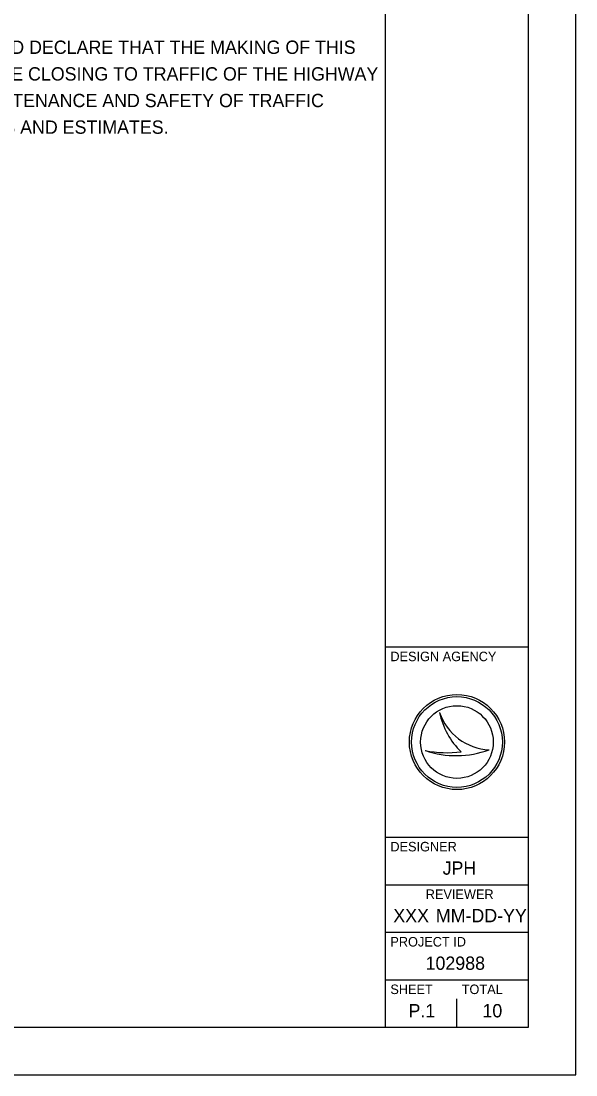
# Model space of a CAD drawing. Extents: x -2.1 to 31.9, y 6.3 to 28.3.
# Drawn here: x 26.1 to 31.93, y 6.34 to 17.42 of the extents above; entities that cross this region are included whole.
import ezdxf

# ---------------------------------------------------------------- set-up
doc = ezdxf.new("R2010")
doc.units = 0
for name, color, linetype in [('SH_Border', 7, 'Continuous'), ('SH_Cut_Line', 7, 'Continuous'), ('SH_Data', 7, 'Continuous')]:
    doc.layers.add(name, color=color, linetype=linetype)

msp = doc.modelspace()

# ---------------------------------------------------------------- linework, layer by layer
at = {"layer": 'SH_Border'}
for p, q in [((29.934, 6.844), (29.934, 27.844)), ((29.934, 10.844), (31.434, 10.844)), ((29.934, 8.844), (31.434, 8.844)), ((29.934, 8.344), (31.434, 8.344)), ((29.934, 7.844), (31.434, 7.844)), ((29.934, 7.344), (31.434, 7.344))]:
    msp.add_line(p, q, dxfattribs=at)
msp.add_lwpolyline([(-0.566, 27.844), (31.434, 27.844), (31.434, 6.844), (-0.566, 6.844)], close=True, dxfattribs=at)
at = {"layer": 'SH_Cut_Line'}
msp.add_lwpolyline([(-2.066, 6.344), (31.934, 6.344), (31.934, 28.344), (-2.066, 28.344)], close=True, dxfattribs=at)
at = {"layer": 'SH_Data'}
for p, q in [((30.502, 10.154), (30.502, 10.154)), ((30.352, 9.753), (30.352, 9.753)), ((30.684, 9.844), (30.684, 9.844)), ((31.022, 9.762), (31.022, 9.762)), ((30.684, 6.844), (30.684, 7.144)), ((30.309, 7.019), (30.309, 7.019))]:
    msp.add_line(p, q, dxfattribs=at)
for radius in [0.5, 0.477, 0.477, 0.382]:
    msp.add_circle((30.684, 9.844), radius, dxfattribs=at)
for centre, radius, start, end in [((31.05, 10.342), 0.58, 198.9257, 198.9319), ((31.281, 10.314), 0.796, 191.6379, 191.6421), ((31.05, 10.342), 0.58, 198.9319, 267.1657), ((31.281, 10.314), 0.796, 191.6421, 226.0947), ((30.674, 10.714), 1.013, 251.4576, 290.0832), ((30.582, 10.998), 1.266, 259.4964, 259.4995), ((30.674, 10.714), 1.013, 251.4527, 251.4576), ((30.582, 10.998), 1.266, 259.4995, 276.6672)]:
    msp.add_arc(centre, radius, start, end, dxfattribs=at)

# ---------------------------------------------------------------- texts
for s, height, p in [(' I HEREBY APPROVE THESE PLANS AND DECLARE THAT THE MAKING OF THIS', 0.14, (22.462, 17.079)), ('IMPROVEMENT WILL NOT REQUIRE THE CLOSING TO TRAFFIC OF THE HIGHWAY', 0.14, (22.462, 16.799)), ('AND THAT PROVISIONS FOR THE MAINTENANCE AND SAFETY OF TRAFFIC', 0.14, (22.462, 16.519)), ('WILL BE AS SET FORTH ON THE PLANS AND ESTIMATES.', 0.14, (22.462, 16.239)), ('DESIGN AGENCY', 0.1, (29.984, 10.694)), ('DESIGNER', 0.1, (29.984, 8.694)), ('JPH', 0.14, (30.533, 8.449)), ('REVIEWER', 0.1, (30.356, 8.194)), ('XXX', 0.14, (30.015, 7.949)), ('MM-DD-YY', 0.14, (30.462, 7.949)), ('PROJECT ID', 0.1, (29.984, 7.694)), ('102988', 0.14, (30.354, 7.449)), ('SHEET', 0.1, (29.984, 7.194)), ('TOTAL', 0.1, (30.734, 7.194)), ('P.1', 0.14, (30.175, 6.949)), ('10', 0.14, (30.952, 6.949))]:
    msp.add_text(s, height=height, dxfattribs=at).set_placement(p)

doc.saveas('drawing.dxf')
